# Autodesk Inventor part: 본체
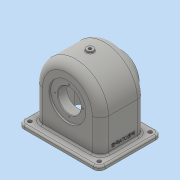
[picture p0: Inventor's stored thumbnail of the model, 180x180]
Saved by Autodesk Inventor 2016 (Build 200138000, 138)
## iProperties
Created: 2022-09
Part Number: 본체
Material: 일반
Document SubType Name: Modeling
Designer: PC-1-10
Density: 1 g/cm^3
Appearance: 기본값
Author: PC-1-10
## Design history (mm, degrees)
sketch "스케치1"
  geometry: L1 (54, 70)-(-54, 70); L2 (-54, 70)-(-54, -70); L3 (-54, -70)-(54, -70); L4 (54, -70)-(54, 70); L5 (-54, 70)-(54, -70); 2 further points
  constraints: 10 end point, 2 parallel, 1 coincident, 1 horizontal, 1 midpoint, 1 perpendicular
  dimensions: "d0" = 140 distance between parallel lines of L3 L1; "d1" = 108 distance between parallel lines of L2 L4
extrude "돌출1" new body sketch "스케치1" distance "d2" = 7; taper "d3" = 0 deg
sketch "스케치2"
  geometry: L1 (0, 57)-(0, -57); L2 (0, -57)-(64, -57); L3 (64, -57)-(64, 57); L4 (64, 57)-(0, 57); L5 (0, -70)-(0, 70) reference; A1 r 57 centre (64, 0) between (64, -57) and (64, 57); 1 further point
  constraints: 8 end point, 3 midpoint, 2 parallel, 2 point on circle, 1 centre point, 1 perpendicular, 1 vertical
  dimensions: "d4" = 57 radius of A1; "d5" = 64 distance between parallel lines of L3 L1
extrude "돌출2" join sketch "스케치2" stored distance "d6" = 78; taper "d7" = 0 deg
fillet "모깎기1" dims "d8" = 14
feature "쉘1" dims "d9" = 5
sketch "스케치3"
  geometry: L1 (15, -22)-(15, -108) reference; L2 (74, -13)-(24, -13) reference; L3 (83, -108)-(83, -22) reference; L4 (24, -117)-(74, -117) reference; L5 (0, 0)-(98, 0) reference; L6 (0, -130)-(0, 0) reference; L7 (98, -130)-(0, -130) reference; L8 (98, 0)-(98, -130) reference; A1 r 9 centre (24, -22) between (24, -13) and (15, -22) reference; A2 r 9 centre (74, -22) between (83, -22) and (74, -13) reference; A3 r 9 centre (74, -108) between (74, -117) and (83, -108) reference; A4 r 9 centre (24, -108) between (15, -108) and (24, -117) reference; 1 further point
extrude "돌출3" join sketch "스케치3" stored distance "d10" = 78; taper "d11" = 0 deg
node "작업 평면1"
sketch "스케치4"
  geometry: L1 (0, -70)-(0, 70) reference; C1 r 31 at (-64, 0); 2 further points
  constraints: 1 centre point, 1 horizontal alignment, 1 midpoint
  dimensions: "d13" = 62 diameter of C1; "d14" = 64 distance from line of C1.centre L1
extrude "돌출4" join sketch "스케치4" stored distance "d15" = 78; taper "d16" = 0 deg
node "작업 평면2"
sketch "스케치5"
  geometry: C1 r 6 at (0, 0); 1 further point
  constraints: 1 centre point, 1 coincident
  dimensions: "d18" = 12 diameter of C1
extrude "돌출5" join sketch "스케치5" stored distance "d19" = 78; taper "d20" = 0 deg
sketch "스케치6"
  geometry: C1 r 28 at (-43, 64); A1 r 43 centre (-43, 64) between (0, 64) and (-86, 64) reference; 1 further point
  constraints: 1 centre point, 1 concentric
  dimensions: "d21" = 56 diameter of C1
extrude "돌출6" join sketch "스케치6" distance "d22" = 14; taper "d23" = 0 deg
feature "면 기울기1" dims angle "d24" = 30 deg
hole "구멍1" diameter "d27" = 40; stored, may be unused: countersink angle "d31" = 90 deg, drill point angle "d33" = 118 deg; dims "d25" = 10, "d26" = 10, "d28" = 6, "d29" = 64, "d30" = 3, "d32" = 29
hole "구멍2" diameter "d36" = 35; stored, may be unused: countersink angle "d40" = 90 deg, drill point angle "d42" = 118 deg; dims "d34" = 10, "d35" = 10, "d37" = 6, "d38" = 40, "d39" = 16, "d41" = 20
hole "구멍3" diameter "d45" = 5.188; stored, may be unused: countersink angle "d49" = 90 deg, drill point angle "d51" = 118 deg; dims "d43" = 10, "d44" = 10, "d46" = 12, "d47" = 40, "d48" = 16, "d50" = 16
sketch "스케치7" dims "d52" = 48
  geometry: C1 r 31 at (0, 0) reference; 3 further points
  constraints: 1 vertical alignment, 3 other
hole "구멍4" sketch "스케치7" at (0, 24) diameter "d53" = 2.459; stored, may be unused: countersink angle "d57" = 90 deg, drill point angle "d59" = 118 deg; dims "d54" = 7, "d55" = 40, "d56" = 16, "d58" = 9
sketch "스케치8"
  geometry: C1 r 24 at (0, 0); C2 r 32 at (0, 0) reference; C3 r 1.23 at (0, 24) reference; 2 further points
  constraints: 1 centre point, 1 coincident, 1 concentric
  dimensions: "d63" = 48 diameter of C1
hole "구멍5" sketch "스케치8" at (0, 24) diameter "d64" = 2.459; stored, may be unused: countersink angle "d68" = 90 deg, drill point angle "d70" = 118 deg; dims "d65" = 7, "d66" = 40, "d67" = 16, "d69" = 9
fillet "모깎기2" dims "d74" = 10
fillet "모깎기3" dims "d75" = 3
fillet "모깎기4" dims "d76" = 1
fillet "모깎기5" dims "d77" = 3
hole "구멍6" diameter "d80" = 6.6; stored, may be unused: countersink angle "d84" = 90 deg, drill point angle "d86" = 118 deg; dims "d78" = 10, "d79" = 10, "d81" = 7, "d82" = 40, "d83" = 16, "d85" = 9
hole "구멍7" diameter "d89" = 6.6; stored, may be unused: countersink angle "d93" = 90 deg, drill point angle "d95" = 118 deg; dims "d87" = 10, "d88" = 10, "d90" = 7, "d91" = 40, "d92" = 16, "d94" = 9
hole "구멍8" diameter "d98" = 6.6; stored, may be unused: countersink angle "d102" = 90 deg, drill point angle "d104" = 118 deg; dims "d96" = 10, "d97" = 10, "d99" = 7, "d100" = 40, "d101" = 16, "d103" = 9
hole "구멍9" diameter "d107" = 6.6; stored, may be unused: countersink angle "d111" = 90 deg, drill point angle "d113" = 118 deg; dims "d105" = 10, "d106" = 10, "d108" = 7, "d109" = 40, "d110" = 16, "d112" = 9
fillet "모깎기6" dims "d114" = 3
fillet "모깎기7" dims "d115" = 3
fillet "모깎기8" dims "d116" = 0.6
chamfer "모따기1" distance "d117" = 1; stored, may be unused: second distance "d118" = 2, angle "d119" = 45 deg
fillet "모깎기9" dims "d120" = 3
node "작업 평면3"
sketch "스케치9"
  geometry: L1 (-25, 22)-(25, 22); L2 (25, 22)-(25, 12); L3 (25, 12)-(-25, 12); L4 (-25, 12)-(-25, 22); L5 (-25, 17)-(25, 17); L6 (0, 12)-(0, 22); L7 (-44, 0)-(44, 0) reference; L8 (-39, 64)-(-39, 10) reference; 1 further point
  constraints: 4 end point, 4 midpoint, 2 other
  dimensions: "d122" = 10 distance between parallel lines of L3 L1; "d123" = 50 distance between parallel lines of L2 L4; "d124" = 17 distance between parallel lines of L5 L7; "d125" = 39 distance between parallel lines of L6 L8
feature "엠보싱1" sketch "스케치9" dims "d126" = 0.5, "d127" = 0
node "솔리드1"
pattern_circular "원형 패턴1" dims angle "d61" = 360 deg
pattern_circular "원형 패턴2" dims angle "d72" = 360 deg
node "투영된 루프1"
other parameters: "d12" = -54, "d17" = 124, "d121" = -110.75
